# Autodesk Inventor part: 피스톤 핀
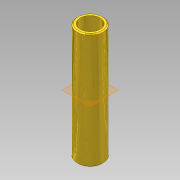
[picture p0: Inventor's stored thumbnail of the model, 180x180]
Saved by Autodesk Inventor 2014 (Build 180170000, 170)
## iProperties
Manager: KYOUNG IL JANG
Company: 한국ATC센터
Created: 2012-10
Part Number: 피스톤 핀
Document SubType Name: Modeling
Density: 1 g/cm^3
Checked By: KYOUNG IL JANG
Vendor: CBT Solutions
Designer: KYOUNG IL JANG
Material: 일반
Appearance: _시험_금속성 금색
Author: KYOUNG IL JANG
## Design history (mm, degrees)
sketch "스케치1"
  geometry: C1 r 6.5 at (0, 0); C2 r 5 at (0, 0); 1 further point
  constraints: 2 centre point, 2 coincident
  dimensions: "d0" = 13 diameter of C1; "d1" = 1.5 radial gap between concentric circles of C1 C2
extrude "돌출1" new body sketch "스케치1" stored distance "d2" = 58; taper "d3" = 0 deg
chamfer "모따기1" distance "d4" = 0.5; stored, may be unused: second distance "d5" = 2, angle "d6" = 45 deg
node "솔리드1"
